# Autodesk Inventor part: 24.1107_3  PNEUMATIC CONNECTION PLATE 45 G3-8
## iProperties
Created: 2007-01
Part Number: 24.1107_3  PNEUMATIC CONNECTION PLATE 45 G3-8
Document SubType Name: Modeling
Designer: Andy Moles
Material: Aluminum-6061
Mass: 146.835 g
Surface Area: 129.958 cm^2
Volume: 54.1826 cm^3
Density: 2.71 g/cm^3
Author: Andy Moles
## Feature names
1. Extrusion1
2. Hole1
3. Hole2
4. Fillet1
5. Revolution1
6. Extrusion2
7. Chamfer1
